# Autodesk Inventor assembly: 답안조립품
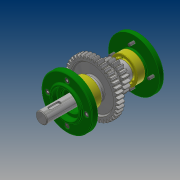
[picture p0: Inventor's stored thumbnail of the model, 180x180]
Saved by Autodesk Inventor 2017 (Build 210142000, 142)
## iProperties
Part Number: 답안조립품
Material: 일반
Document SubType Name: Assembly
Designer: 20
Author: 20
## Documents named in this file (9)
- C:\Users\20\Desktop\480310V1008\답안조립품.iam
- C:\Users\20\Desktop\480310V1008\본체.ipt
- C:\Users\20\Desktop\480310V1008\뒤커버.ipt
- C:\Users\20\Desktop\480310V1008\앞커버.ipt
- C:\Users\20\Desktop\480310V1008\볼트 M4.ipt
- C:\Users\20\Desktop\480310V1008\베어링 6203.ipt
- C:\Users\20\Desktop\480310V1008\축.ipt
- C:\Users\20\Desktop\480310V1008\키 6x6x22.ipt
- C:\Users\20\Desktop\480310V1008\스퍼기어.ipt
